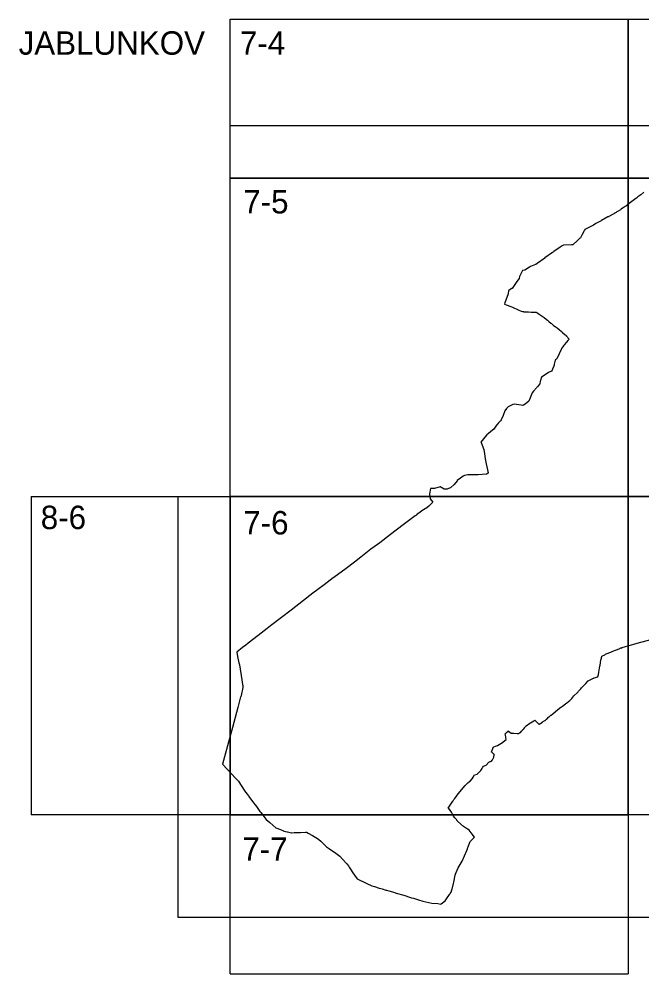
# Model space of a CAD drawing. Extents: x -449577 to -436680, y -1132317 to -1125726.
# Drawn here: x -439662.6 to -439418.1, y -1130325 to -1129950 of the extents above; entities that cross this region are included whole.
import ezdxf

# ---------------------------------------------------------------- set-up
doc = ezdxf.new("R2010")
doc.units = 0
for name, color, linetype in [('Vrstva 1', 7, 'Continuous'), ('Vrstva 10', 7, 'Continuous'), ('Vrstva 4', 7, 'Continuous')]:
    doc.layers.add(name, color=color, linetype=linetype)

msp = doc.modelspace()

# ---------------------------------------------------------------- linework, layer by layer
at = {"layer": 'Vrstva 1'}
for points in [[(-439417.37, -1130018), (-439418.58, -1130018.96), (-439418.58, -1130018.96), (-439419.73, -1130019.83), (-439420.3, -1130020.26), (-439420.88, -1130020.7), (-439421.04, -1130020.82), (-439423.17, -1130022.46), (-439424.24, -1130023.28), (-439424.71, -1130023.62), (-439425.47, -1130024.13), (-439425.72, -1130024.29), (-439426.31, -1130024.68), (-439426.35, -1130024.71), (-439426.56, -1130024.85), (-439427.47, -1130025.45), (-439427.48, -1130025.45), (-439427.95, -1130025.71), (-439428.1, -1130025.79), (-439428.28, -1130025.89), (-439428.74, -1130026.14), (-439428.92, -1130026.25), (-439429.08, -1130026.34), (-439429.18, -1130026.4), (-439429.42, -1130026.54), (-439431.08, -1130027.48), (-439431.25, -1130027.57), (-439431.48, -1130027.7), (-439433.95, -1130029.1), (-439434.07, -1130029.17), (-439436.18, -1130030.3), (-439437.2, -1130030.85), (-439440.54, -1130032.66), (-439440.71, -1130032.96), (-439440.77, -1130033.07), (-439441.55, -1130034.53), (-439442.23, -1130035.85), (-439442.37, -1130035.98), (-439442.46, -1130036.06), (-439443.6, -1130037.1), (-439445.11, -1130038.48), (-439445.28, -1130038.63), (-439445.28, -1130038.64), (-439445.75, -1130038.65), (-439448.94, -1130038.74), (-439448.95, -1130038.74), (-439449.38, -1130039.03), (-439450.21, -1130039.6), (-439452.68, -1130041.26), (-439452.72, -1130041.28), (-439452.96, -1130041.46), (-439453.23, -1130041.66), (-439456.21, -1130043.79), (-439456.28, -1130043.84), (-439459.28, -1130046.02), (-439459.75, -1130046.36), (-439459.91, -1130046.42), (-439461.85, -1130047.14), (-439461.86, -1130047.14), (-439462.25, -1130047.38), (-439464.13, -1130048.54), (-439465.05, -1130048.75), (-439465.3, -1130049.26), (-439466.06, -1130050.77), (-439466.07, -1130050.78), (-439466.14, -1130051.04), (-439466.34, -1130051.88), (-439467.17, -1130052.99), (-439468.54, -1130054.94), (-439469.1, -1130055.75), (-439469.13, -1130055.77), (-439470.29, -1130056.41), (-439470.39, -1130056.47), (-439470.46, -1130056.86), (-439470.61, -1130057.67), (-439470.66, -1130057.86), (-439471.95, -1130061.44), (-439472.12, -1130061.92), (-439472.09, -1130061.91), (-439472.07, -1130061.9), (-439471.39, -1130062.16), (-439469.58, -1130062.82), (-439468.96, -1130063.11), (-439466.67, -1130064.19), (-439466.65, -1130064.19), (-439465.49, -1130064.66), (-439465.02, -1130064.84), (-439464.99, -1130064.85), (-439464.56, -1130064.88), (-439464.42, -1130064.89), (-439464.2, -1130064.91), (-439462.6, -1130065.01), (-439461.56, -1130065.08), (-439460.51, -1130065.05), (-439459.67, -1130065.02), (-439459.66, -1130065.02), (-439459.38, -1130065.17), (-439459.01, -1130065.43), (-439458.46, -1130065.81), (-439458.07, -1130066.09), (-439456.51, -1130067.23), (-439456.34, -1130067.35), (-439455.23, -1130068.27), (-439454.84, -1130068.59), (-439454.66, -1130068.74), (-439453.91, -1130069.35), (-439453.64, -1130069.58), (-439453.04, -1130070.07), (-439452.82, -1130070.25), (-439452.18, -1130070.67), (-439451.43, -1130071.17), (-439451.4, -1130071.19), (-439450.64, -1130071.87), (-439449.76, -1130072.65), (-439449.32, -1130073.03), (-439448.31, -1130073.92), (-439448.05, -1130074.15), (-439448, -1130074.2), (-439447.9, -1130074.3), (-439447.89, -1130074.31), (-439447.8, -1130074.41), (-439447.77, -1130074.44), (-439446.72, -1130075.67), (-439446.73, -1130075.68), (-439447.17, -1130076.17), (-439447.23, -1130076.24), (-439447.8, -1130076.87), (-439448.62, -1130077.93), (-439448.79, -1130078.14), (-439449.35, -1130078.86), (-439449.65, -1130079.39), (-439449.67, -1130079.43), (-439449.68, -1130079.45), (-439449.81, -1130079.73), (-439450.61, -1130081.4), (-439450.92, -1130082.04), (-439451.54, -1130083.33), (-439451.65, -1130083.57), (-439451.66, -1130083.57), (-439451.7, -1130083.6), (-439451.99, -1130083.8), (-439452.07, -1130083.84), (-439452.12, -1130083.94), (-439452.21, -1130084.14), (-439452.3, -1130084.42), (-439452.47, -1130084.98), (-439452.48, -1130085), (-439452.6, -1130085.5), (-439452.62, -1130085.57), (-439452.61, -1130085.63), (-439452.6, -1130085.71), (-439452.6, -1130085.78), (-439452.61, -1130085.83), (-439453.49, -1130088.16), (-439453.51, -1130088.21), (-439453.53, -1130088.25), (-439453.54, -1130088.26), (-439454.24, -1130088.56), (-439454.49, -1130088.67), (-439454.96, -1130088.91), (-439457.57, -1130090.6), (-439457.57, -1130090.6), (-439457.94, -1130091.91), (-439458.02, -1130092.17), (-439458.13, -1130092.59), (-439458.19, -1130092.8), (-439458.19, -1130092.81), (-439458.18, -1130092.81), (-439458.01, -1130092.97), (-439458.02, -1130092.98), (-439458.38, -1130093.37), (-439459.18, -1130094.37), (-439459.19, -1130094.38), (-439459.4, -1130094.63), (-439459.4, -1130094.64), (-439459.52, -1130094.79), (-439460.68, -1130096.14), (-439461.22, -1130096.77), (-439461.98, -1130098.72), (-439462.36, -1130099.74), (-439462.49, -1130100.09), (-439464.02, -1130101.19), (-439464.64, -1130101.63), (-439464.82, -1130101.67), (-439464.84, -1130101.67), (-439465.47, -1130101.58), (-439468.31, -1130101.16), (-439468.8, -1130101.4), (-439470.13, -1130102.04), (-439470.67, -1130102.3), (-439470.7, -1130102.33), (-439471.13, -1130102.74), (-439471.3, -1130102.96), (-439471.96, -1130103.81), (-439471.96, -1130103.82), (-439472.63, -1130105.62), (-439473.2, -1130107.12), (-439473.2, -1130107.12), (-439473.34, -1130107.34), (-439473.67, -1130107.71), (-439474.39, -1130108.51), (-439475.09, -1130109.28), (-439475.1, -1130109.3), (-439475.23, -1130109.49), (-439476.3, -1130111.06), (-439476.77, -1130111.44), (-439478.34, -1130112.7), (-439479.01, -1130113.24), (-439479.11, -1130113.32), (-439479.14, -1130113.36), (-439480.26, -1130114.79), (-439481.4, -1130116.1), (-439481.25, -1130116.27), (-439481.24, -1130116.3), (-439481.24, -1130116.31), (-439480.23, -1130119.07), (-439479.95, -1130120.73), (-439479.63, -1130122.68), (-439479.22, -1130124.64), (-439478.49, -1130128.14), (-439478.45, -1130128.34), (-439479.1, -1130128.68), (-439479.22, -1130128.75), (-439482.39, -1130129.01), (-439482.55, -1130129.01), (-439484.04, -1130128.98), (-439486.43, -1130128.96), (-439487.71, -1130129.23), (-439488.31, -1130129.5), (-439489.29, -1130130.3), (-439490.59, -1130131.17), (-439490.68, -1130131.28), (-439491.84, -1130132.7), (-439493.29, -1130134.04), (-439493.98, -1130134.36), (-439494.58, -1130134.64), (-439495.75, -1130134.57), (-439497.36, -1130133.72), (-439499.6, -1130134.39), (-439501.08, -1130134.36), (-439501.46, -1130136.47), (-439501.47, -1130136.49), (-439501.48, -1130136.58), (-439501.19, -1130138.39), (-439500.22, -1130139.71), (-439500.21, -1130139.73), (-439500.95, -1130140.48), (-439501.56, -1130141.04), (-439501.81, -1130141.27), (-439502.61, -1130141.9), (-439504.54, -1130143.13), (-439504.6, -1130143.17), (-439506.57, -1130144.7), (-439506.63, -1130144.74), (-439507.12, -1130145.12), (-439511.78, -1130148.58), (-439511.81, -1130148.61), (-439516.76, -1130152.37), (-439521.02, -1130155.62), (-439521.9, -1130156.28), (-439524.47, -1130158.22), (-439528.47, -1130161.35), (-439530.91, -1130163.22), (-439534.22, -1130165.75), (-439534.27, -1130165.79), (-439539.06, -1130169.3), (-439539.29, -1130169.48), (-439542.9, -1130172.16), (-439545.29, -1130173.98), (-439547.26, -1130175.46), (-439549.58, -1130177.21), (-439549.81, -1130177.38), (-439550.94, -1130178.27), (-439555.76, -1130182.07), (-439559.65, -1130185.02), (-439563.87, -1130188.27), (-439565.16, -1130189.27), (-439567.55, -1130191.15), (-439568.73, -1130192.07), (-439572.67, -1130195.12), (-439573.6, -1130195.83), (-439574.84, -1130196.79), (-439577.16, -1130198.59), (-439577.16, -1130198.59), (-439577.12, -1130198.77), (-439576.83, -1130200.15), (-439576.8, -1130200.31), (-439576.27, -1130202.85), (-439576.11, -1130203.58), (-439576.11, -1130203.62), (-439575.18, -1130209.5), (-439575.17, -1130209.53), (-439574.87, -1130211.26), (-439574.87, -1130211.28), (-439574.81, -1130211.65), (-439574.75, -1130212.07), (-439574.78, -1130212.44), (-439574.93, -1130213.17), (-439575.31, -1130214.96), (-439575.6, -1130216.14), (-439575.62, -1130216.19), (-439576.73, -1130220.36), (-439578.83, -1130228.24), (-439580.82, -1130235.46), (-439582.75, -1130242.56), (-439582.76, -1130242.6), (-439577.48, -1130248.2), (-439576.43, -1130249.33), (-439575.67, -1130250.55), (-439573.65, -1130253.61), (-439573.6, -1130253.68), (-439572.59, -1130255.09), (-439572.43, -1130255.3), (-439570.55, -1130257.78), (-439569.98, -1130258.52), (-439569.95, -1130258.56), (-439569.43, -1130259.28), (-439568.05, -1130261.18), (-439567.72, -1130261.63), (-439565.57, -1130264.35), (-439564.17, -1130265.57), (-439561.77, -1130267.55), (-439560.03, -1130268.3), (-439558.84, -1130268.82), (-439558.71, -1130268.87), (-439557.38, -1130269.15), (-439557.24, -1130269.18), (-439555.62, -1130269.51), (-439555.59, -1130269.51), (-439554.63, -1130269.49), (-439554.25, -1130269.49), (-439553.73, -1130269.48), (-439553.05, -1130269.47), (-439552.14, -1130269.43), (-439550.19, -1130269.27), (-439549.74, -1130269.34), (-439549.08, -1130269.69), (-439547.36, -1130270.64), (-439545.4, -1130271.74), (-439544.88, -1130272.22), (-439544.16, -1130272.9), (-439543.36, -1130273.65), (-439542.04, -1130274.95), (-439541.9, -1130275.05), (-439540.71, -1130275.9), (-439538.3, -1130277.61), (-439536.66, -1130278.79), (-439535.61, -1130279.97), (-439533.97, -1130281.79), (-439533.33, -1130282.5), (-439532.97, -1130283.09), (-439532.51, -1130283.83), (-439531.57, -1130285.3), (-439530.94, -1130286.22), (-439529.9, -1130287.66), (-439528.83, -1130288.17), (-439527.45, -1130288.82), (-439526.14, -1130289.43), (-439524.17, -1130290.32), (-439523.04, -1130290.67), (-439521.32, -1130291.24), (-439521.17, -1130291.29), (-439520.08, -1130291.61), (-439518.66, -1130292.03), (-439518.65, -1130292.03), (-439518.44, -1130292.09), (-439518.38, -1130292.11), (-439517.52, -1130292.37), (-439515.13, -1130293.06), (-439515.01, -1130293.1), (-439514.53, -1130293.24), (-439511.6, -1130294.11), (-439508.91, -1130294.94), (-439508.57, -1130295.04), (-439507.81, -1130295.27), (-439505.8, -1130295.89), (-439504.07, -1130296.44), (-439500.61, -1130297.18)], [(-439500.61, -1130297.18), (-439498.22, -1130297.37), (-439497.02, -1130297.6), (-439496.91, -1130297.51), (-439495.33, -1130296.24), (-439494.3, -1130294.76), (-439494.19, -1130294.61), (-439493.67, -1130293.85), (-439493.56, -1130293.68), (-439493.42, -1130293.45), (-439493.04, -1130292.82), (-439492.77, -1130291.99), (-439492.75, -1130291.92), (-439492.73, -1130291.87), (-439492.7, -1130291.76), (-439492.67, -1130291.67), (-439492.67, -1130291.66), (-439492.04, -1130289.46), (-439491.9, -1130288.94), (-439491.45, -1130286.19), (-439491.45, -1130286.19), (-439491.26, -1130285.75), (-439491, -1130285.13), (-439490.21, -1130283.3), (-439488.64, -1130280.65), (-439486.89, -1130276.52), (-439486.57, -1130275.88), (-439486.53, -1130275.75), (-439486.14, -1130274.65), (-439485.55, -1130272.98), (-439483.87, -1130271.27), (-439484.8, -1130270.03), (-439484.86, -1130269.94), (-439484.91, -1130269.88), (-439484.94, -1130269.84), (-439485.01, -1130269.74), (-439485.06, -1130269.66), (-439485.14, -1130269.54), (-439485.5, -1130269.02), (-439485.87, -1130268.56), (-439486.44, -1130268.19), (-439486.54, -1130268.13), (-439488.19, -1130267.06), (-439490.38, -1130265.12), (-439490.51, -1130264.95), (-439490.54, -1130264.91), (-439490.62, -1130264.81), (-439490.96, -1130264.39), (-439491.29, -1130263.98), (-439491.55, -1130263.66), (-439492.03, -1130263.07), (-439492.11, -1130262.97), (-439492.61, -1130262.01), (-439492.9, -1130261.45), (-439493.13, -1130261.02), (-439493.18, -1130260.93), (-439493.22, -1130260.88), (-439493.48, -1130260.59), (-439493.68, -1130260.36), (-439493.94, -1130260.07), (-439494.16, -1130259.82), (-439492.3, -1130257.08), (-439492.21, -1130256.96), (-439491.89, -1130256.51), (-439491.57, -1130256.07), (-439490.24, -1130254.24), (-439487.56, -1130250.98), (-439487.21, -1130250.66), (-439486.5, -1130249.96), (-439486.39, -1130249.87), (-439486.2, -1130249.73), (-439485.6, -1130249.25), (-439484.74, -1130248.41), (-439484.33, -1130247.65), (-439483.86, -1130246.78), (-439482.81, -1130246.54), (-439481.41, -1130245.11), (-439480.87, -1130244.26), (-439480.86, -1130244.25), (-439480.86, -1130244.23), (-439480.65, -1130243.9), (-439480.6, -1130243.82), (-439480.36, -1130243.43), (-439479.2, -1130242.99), (-439478.18, -1130241.81), (-439477.65, -1130241.61), (-439477.53, -1130241.56), (-439477.11, -1130241.4), (-439476.89, -1130241.01), (-439476.84, -1130240.92), (-439476.67, -1130240.62), (-439476.26, -1130239.88), (-439476.06, -1130238.97), (-439476.06, -1130238.95), (-439476.05, -1130238.94), (-439477.1, -1130237.95), (-439477.12, -1130237.94), (-439477.13, -1130237.92), (-439477.18, -1130237.88), (-439476.53, -1130236.08), (-439476.46, -1130235.88), (-439476.3, -1130235.82), (-439475.57, -1130235.53), (-439474.88, -1130235.26), (-439474.76, -1130235.21), (-439473.55, -1130234.5), (-439473.43, -1130234.42), (-439473.43, -1130234.42), (-439473.42, -1130234.41), (-439473.3, -1130234.34), (-439471.44, -1130232.94), (-439471.44, -1130232.9), (-439471.47, -1130232.74), (-439471.54, -1130232.26), (-439471.6, -1130231.91), (-439471.7, -1130231.29), (-439471.72, -1130231.18), (-439471.74, -1130231.05), (-439471.76, -1130230.88), (-439471.79, -1130230.74), (-439471.25, -1130230.18), (-439470.69, -1130229.61), (-439470.65, -1130229.56), (-439470.51, -1130229.66), (-439469.51, -1130230.45), (-439468.83, -1130230.46), (-439468.77, -1130230.46), (-439468.52, -1130230.47), (-439468.36, -1130230.47), (-439467.05, -1130230.49), (-439466.42, -1130230.51), (-439466.15, -1130230.35), (-439466.12, -1130230.33), (-439466, -1130230.26), (-439465.86, -1130230.17), (-439465.82, -1130230.14), (-439465.28, -1130229.54), (-439465.17, -1130229.42), (-439465.08, -1130229.32), (-439464.91, -1130229.14), (-439464.83, -1130229.05), (-439464.72, -1130228.93), (-439464.69, -1130228.89), (-439464.66, -1130228.86), (-439464.61, -1130228.8), (-439464.52, -1130228.69), (-439464.12, -1130228.19), (-439463.91, -1130227.93), (-439463.66, -1130227.61), (-439463.55, -1130227.53), (-439462.09, -1130226.46), (-439461.88, -1130226.33), (-439460.52, -1130225.56), (-439460.12, -1130225.33), (-439460.12, -1130225.33), (-439459.98, -1130225.48), (-439459.27, -1130226.19), (-439458.9, -1130226.57), (-439458.72, -1130226.74), (-439458.57, -1130226.89), (-439458.48, -1130226.85), (-439457.2, -1130226.08), (-439457.11, -1130226.03), (-439456.18, -1130225.47), (-439456.14, -1130225.44), (-439455.81, -1130225.15), (-439455.76, -1130225.11), (-439455.59, -1130224.96), (-439455.58, -1130224.95), (-439455.58, -1130224.95), (-439455.54, -1130224.91), (-439455.5, -1130224.87), (-439454.61, -1130224.06), (-439454.59, -1130224.05), (-439454, -1130223.51), (-439453.89, -1130223.42), (-439453.78, -1130223.32), (-439453.78, -1130223.32), (-439453.77, -1130223.32), (-439453.77, -1130223.32), (-439453.77, -1130223.31), (-439453.76, -1130223.31), (-439453.75, -1130223.3), (-439453.75, -1130223.3), (-439453.74, -1130223.29), (-439453.74, -1130223.29), (-439453.73, -1130223.29), (-439453.73, -1130223.29), (-439453.15, -1130222.8), (-439451.16, -1130221.12), (-439449.96, -1130220.27), (-439449.84, -1130220.19), (-439449.79, -1130220.15), (-439449.77, -1130220.14), (-439449.72, -1130220.11), (-439449.36, -1130219.84), (-439448.12, -1130218.9), (-439447.94, -1130218.76), (-439447.73, -1130218.6), (-439447.71, -1130218.58), (-439446.83, -1130217.91), (-439446.48, -1130217.64), (-439446.43, -1130217.58), (-439446.34, -1130217.48), (-439445.7, -1130216.8), (-439444.8, -1130215.82), (-439443.44, -1130214.41), (-439443.22, -1130214.18), (-439442.97, -1130213.9), (-439442.13, -1130212.95), (-439441.84, -1130212.63), (-439441.64, -1130212.42), (-439441.35, -1130212.1), (-439440.17, -1130210.91), (-439439.24, -1130209.89), (-439437.18, -1130208.88), (-439437.02, -1130208.83), (-439436.82, -1130208.75), (-439435.38, -1130208.26), (-439435.23, -1130207.39), (-439435.07, -1130206.52), (-439434.65, -1130204.15), (-439434.57, -1130203.68), (-439434.24, -1130201.8), (-439434.04, -1130200.92), (-439434.01, -1130200.8), (-439433.96, -1130200.61), (-439433.95, -1130200.57), (-439433.93, -1130200.5), (-439433.92, -1130200.46), (-439433.91, -1130200.41), (-439433.9, -1130200.37), (-439433.89, -1130200.35), (-439433.83, -1130200.14), (-439432.75, -1130199.6), (-439432.46, -1130199.46), (-439432.44, -1130199.45), (-439432.19, -1130199.32), (-439432.14, -1130199.3), (-439430.37, -1130198.58), (-439430.34, -1130198.57), (-439430.31, -1130198.55), (-439429.51, -1130198.24), (-439428.55, -1130197.84), (-439427.74, -1130197.5), (-439426.8, -1130197.11), (-439426.72, -1130197.08), (-439426.11, -1130196.84), (-439426.26, -1130197), (-439426.02, -1130196.91), (-439425.53, -1130196.71), (-439425, -1130196.55), (-439423.3, -1130196.03), (-439422.71, -1130195.86), (-439422.26, -1130195.74), (-439421.37, -1130195.49), (-439420.06, -1130195.11), (-439418.52, -1130194.65), (-439414.98, -1130193.78)]]:
    msp.add_lwpolyline(points, dxfattribs=at)
at = {"layer": 'Vrstva 10'}
msp.add_lwpolyline([(-439267.22, -1129991.79), (-439267.22, -1130302.77), (-439600.09, -1130302.77), (-439600.09, -1130137.47), (-439579.72, -1130137.47), (-439579.72, -1130012.47), (-439579.72, -1129991.79), (-439267.22, -1129991.79)], dxfattribs=at)
at = {"layer": 'Vrstva 4'}
for p, q in [((-439579.72, -1129949.97), (-439267.22, -1129949.97)), ((-439657.85, -1130137.47), (-439657.85, -1130262.47)), ((-439579.72, -1130324.97), (-439423.47, -1130324.97))]:
    msp.add_line(p, q, dxfattribs=at)
for points in [[(-439423.47, -1129949.97), (-439423.47, -1130012.47), (-439579.72, -1130012.47), (-439579.72, -1129949.97)], [(-439267.22, -1129949.97), (-439267.22, -1130012.47), (-439423.47, -1130012.47), (-439423.47, -1129949.97)], [(-439657.85, -1130137.47), (-439579.72, -1130137.47), (-439579.72, -1130262.47), (-439657.85, -1130262.47)], [(-439579.72, -1130324.97), (-439579.72, -1130262.47), (-439423.47, -1130262.47), (-439423.47, -1130324.97)]]:
    msp.add_lwpolyline(points, dxfattribs=at)
for points in [[(-439423.47, -1130012.47), (-439423.47, -1130137.47), (-439579.72, -1130137.47), (-439579.72, -1130012.47)], [(-439267.22, -1130012.47), (-439267.22, -1130137.47), (-439423.47, -1130137.47), (-439423.47, -1130012.47)], [(-439423.47, -1130137.47), (-439423.47, -1130262.47), (-439579.72, -1130262.47), (-439579.72, -1130137.47)], [(-439267.22, -1130137.47), (-439267.22, -1130262.47), (-439423.47, -1130262.47), (-439423.47, -1130137.47)]]:
    msp.add_lwpolyline(points, close=True, dxfattribs=at)

# ---------------------------------------------------------------- texts
at = {"layer": 'Vrstva 1'}
for s, p in [('JABLUNKOV', (-439662.76, -1129963.97)), ('7-4', (-439575.91, -1129963.97)), ('7-5', (-439574.6, -1130026.31)), ('8-6', (-439654.07, -1130150.28)), ('7-6', (-439574.6, -1130152.38)), ('7-7', (-439574.96, -1130280.55))]:
    msp.add_text(s, height=9.2, dxfattribs=at).set_placement(p)

doc.saveas('drawing.dxf')
